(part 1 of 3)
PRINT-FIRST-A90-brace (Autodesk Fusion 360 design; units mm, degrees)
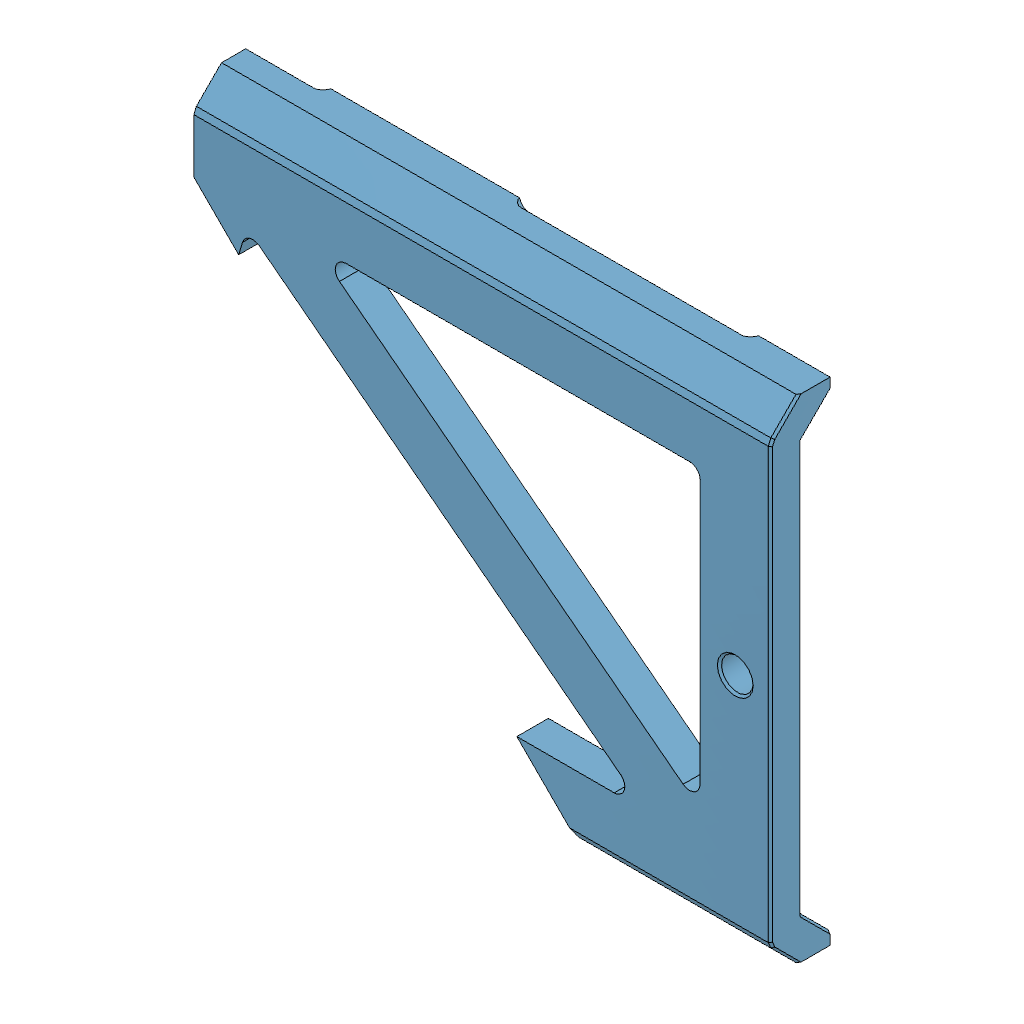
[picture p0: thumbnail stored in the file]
part number: 2026-11-02-20-17-55-344
part number: 2026-11-02-20-17-59-218
part number: 2026-11-02-20-17-59-224
part number: 2026-11-02-20-19-00-695
part number: 2026-11-02-20-19-03-009
part number: 2026-11-02-20-19-04-949
part number: 2026-11-02-20-19-06-912
part number: 2026-11-02-20-19-11-903
part number: 2026-11-02-20-19-12-666
part number: 2026-11-02-20-19-12-978
part number: 2026-11-02-20-19-13-740
part number: 2026-11-02-20-19-14-532
part number: 2026-11-02-20-19-15-361
part number: 2026-11-02-20-19-17-468
part number: 2026-11-02-20-19-19-583
part number: 2026-11-02-20-19-25-638
part number: 2026-11-02-20-19-39-091
parameter "bodyWidth" = 150 comment "Regular octagon across flats; corner diameter is larger."
parameter "bodyLength" = 260 comment "Overall straight length of the shared master blank."
parameter "splitAngle" = 45 comment "Keep this lesson angle at45 degrees."
parameter "faceGap" = 1 comment "Gap between the two printed joint faces."
parameter "wall" = 4.5 comment "Integrated shell and side brace radial thickness."
parameter "faceHalfWidth" = 31.066 (= "bodyWidth * ( sqrt(2) - 1 ) / 2") comment "Half-width of each outer planar facet."
parameter "memberWidth" = 8 comment "Nominal brace and corner chord width in a facet."
parameter "nodeHalfWidth" = 27.066 (= "faceHalfWidth - memberWidth / 2") comment "Chord centerlines measured from facet center."
parameter "jointNodeQ" = 7 comment "First truss skeleton row from the center joint plane."
parameter "endRim" = 10 comment "Uncut axial rim at each distant end."
parameter "endNodeX" = 124 (= "bodyLength / 2 - endRim + memberWidth / 2") comment "Last skeleton row before aperture inset."
parameter "apertureRadius" = 1.5 comment "Rounded internal corners at triangular openings."
parameter "spokeWidth" = 10 comment "Width of each deep bearing bulkhead spoke."
parameter "spokeDepth" = 18 comment "Bulkhead depth normal to the diagonal joint face."
parameter "carrierOD" = 52 comment "Outside of integrated A front bearing carrier."
parameter "rearCarrierClearance" = 46 comment "Internal carrier relief above front bearing shoulder."
parameter "tubeCornerChamfer" = 0.5 comment "Exposed outside octagon corner bevel."
parameter "tubeRimChamfer" = 0.3 comment "End rim and print-contact edge relief."
parameter "cordStation" = 125 (= "bodyLength / 2 - endRim / 2") comment "Load-test cord port center measured along body X."
parameter "bearingOD" = 22 comment "608 measured outside diameter."
parameter "bearingID" = 8 comment "608 bore."
parameter "bearingWidth" = 7 comment "608 width."
parameter "seatAllowance" = 0.2 comment "Trial DIAMETRAL clearance; choose with printed coupon."
parameter "seatDiameter" = 22.2 (= "bearingOD + seatAllowance") comment "Measured fit controls this."
parameter "coreOD" = 44 comment "Bearing holder outer diameter."
parameter "raceRelief" = 19.5 comment "Outer-ring shoulder opening; verify seals."
parameter "frontSeatDepth" = 7.1 comment "0.1 mm outer-ring axial allowance."
parameter "rearSeatDepth" = 7.2 comment "0.2 mm outer-ring axial float."
parameter "shoulder" = 3 comment "Backing behind each bearing seat."
parameter "supportSpacer" = 12 comment "Purchased metal M3 spacer length."
parameter "supportCircle" = 34 comment "Three M3 support bolts."
parameter "supportSpacerOD" = 6 comment "Purchased spacer outside diameter."
parameter "capThickness" = 3 comment "Both printed outer-ring retaining caps."
parameter "m3Clearance" = 3.3 comment "M3 through holes."
parameter "m4Clearance" = 4.3 comment "M4 through holes."
parameter "qFront" = 0.5 (= "faceGap / 2") comment "Front bearing starts at A mating face."
parameter "qFrontBack" = 10.6 (= "qFront + frontSeatDepth + shoulder") comment "End of integrated A holder."
parameter "qRearBase" = 22.6 (= "qFrontBack + supportSpacer") comment "Start of removable rear holder."
parameter "qRearBearing" = 25.6 (= "qRearBase + shoulder") comment "Rear bearing inner end."
parameter "qRearEnd" = 32.8 (= "qRearBearing + rearSeatDepth") comment "Rear holder outer end."
parameter "bearingSpacing" = 25.1 (= "qRearBearing - qFront") comment "Derived support-center spacing, not a bearing rating."
parameter "mountOD" = 76 comment "B mount and F flange outside diameter."
parameter "mountCircle" = 64 comment "Four M4 attachment holes."
parameter "mountOpening" = 50.3 comment "B through opening."
parameter "hubFace" = -23 comment "Metal hub flat mounting face."
parameter "adapterThickness" = 6 comment "F flange and metal compression sleeve length."
parameter "pilotDiameter" = 50 comment "F shallow centering pilot."
parameter "pilotInside" = 34 comment "Clearance around metal hub."
parameter "pilotHeight" = 2 comment "Short pilot only."
parameter "hubHoleSpacing" = 16 comment "Metal Sonic hub square hole spacing."
parameter "sleeveOD" = 8 comment "M4 metal compression sleeves."
parameter "sleeveAllowance" = 0.2 comment "Trial DIAMETRAL sleeve clearance."
parameter "shaftClearance" = 8.5 comment "F clearance hole; not a bearing."
parameter "nutAF" = 7.2 comment "M4 nominal 7 AF nut trial pocket."
parameter "nutDepth" = 4 comment "Open front M4 nut pocket."
parameter "rootRadius" = 1 comment "Hub-to-wall blend."
parameter "entryChamfer" = 0.4 comment "Assembly lead-in."
parameter "bedRelief" = 0.3 comment "Bed-contact edge allowance."
parameter "driverPort" = 5 comment "Clearance for bare3 mm hex-key shafts; bulky bit holders do not fit."
parameter "accessPadWidth" = 12 comment "Reinforced access-port capsule width."
parameter "accessPadExtra" = 2 comment "Local inward reinforcement beyond nominal side wall."
sketch "01 Master Octagon" plane through (0, 0, 0) normal (1, 0, 0) x axis (0, 0, -1)
  line L1 (31.066, 75) -> (75, 31.066)
  line L2 (-31.066, 75) -> (31.066, 75)
  line L3 (-75, 31.066) -> (-31.066, 75)
  line L4 (-75, -31.066) -> (-75, 31.066)
  line L5 (-31.066, -75) -> (-75, -31.066)
  line L6 (31.066, -75) -> (-31.066, -75)
  line L7 (75, -31.066) -> (31.066, -75)
  line L8 (75, 31.066) -> (75, -31.066)
  point P1 (0, 0)
  point P10 (0, 0)
  point P3 (31.066, 75)
  point P8 (31.066, -75)
  coincident P1 P10
  horizontal L2
  dimension "d59" distance P3 P8 = 150 (= "bodyWidth")
extrude "Extrude1" new body sketch "01 Master Octagon" distance 260 (= "bodyLength")
work_plane "WorkPlane1" RotateAngle 45 (= "splitAngle") ExtraOffset 0
split "Split1"
offset_faces "OffsetFaces1" distance -0.5 (= "-faceGap / 2")
offset_faces "OffsetFaces2" distance -0.5 (= "-faceGap / 2")
component_from_bodies "Body->Comp1"
component_from_bodies "Body->Comp2"
shell "Shell1" innerThickness 4.5 (= "wall")
shell "Shell1" innerThickness 4.5 (= "wall")
work_plane "WorkPlane1" RotateAngle -90 ExtraOffset 0
work_plane "WorkPlane2" AlongDistance 75 (= "bodyWidth / 2") ExtraOffset 0
sketch "A Facet 0 Triangle 1" plane through (0, 75, 0) normal (0, 1, 0) x axis (1, 0, 0)
  line L1 (-65.1005, -27.066) -> (-65.1005, 27.066)
  line L2 (60.9665, 27.066) -> (-65.1005, -27.066)
  line L3 (-65.1005, 27.066) -> (60.9665, 27.066)
  line L4 (-61.1005, -20.9953) -> (-61.1005, 23.066)
  line L5 (41.513, 23.066) -> (-61.1005, -20.9953)
  line L6 (-61.1005, 23.066) -> (41.513, 23.066)
  point P1 (0, 0)
  point P2 (-65.1005, 27.066)
  point P3 (-65.1005, -27.066)
  point P4 (60.9665, 27.066)
  dimension "d72" distance P1 P2 = 65.1005 (= "Linear Dimension-2")
  dimension "d73" distance P1 P2 = 27.066 (= "Linear Dimension-3")
  dimension "d74" distance P1 P3 = 65.1005 (= "Linear Dimension-4")
  dimension "d75" distance P1 P3 = 27.066 (= "Linear Dimension-5")
  dimension "d76" distance P1 P4 = 60.9665 (= "Linear Dimension-6")
  dimension "d77" distance P1 P4 = 27.066 (= "Linear Dimension-7")
  dimension "d78" = -4 (= "-memberWidth / 2")
extrude "Extrude1" cut sketch "A Facet 0 Triangle 1" profile of L5 L6 L4 against normal blind 4.7 (magnitude of "-( wall + 0.2 mm )")
sketch "A Facet 0 Triangle 2" plane through (0, 75, 0) normal (0, 1, 0) x axis (1, 0, 0)
  line L1 (60.9665, 27.066) -> (-65.1005, -27.066)
  line L2 (92.4832, -27.066) -> (60.9665, 27.066)
  line L3 (-65.1005, -27.066) -> (92.4832, -27.066)
  line L4 (59.2912, 21.9935) -> (-45.647, -23.066)
  line L5 (85.5258, -23.066) -> (59.2912, 21.9935)
  line L6 (-45.647, -23.066) -> (85.5258, -23.066)
  point P1 (0, 0)
  point P2 (-65.1005, -27.066)
  point P3 (60.9665, 27.066)
  point P4 (92.4832, -27.066)
  dimension "d81" distance P1 P2 = 65.1005 (= "Linear Dimension-2")
  dimension "d82" distance P1 P2 = 27.066 (= "Linear Dimension-3")
  dimension "d83" distance P1 P3 = 60.9665 (= "Linear Dimension-4")
  dimension "d84" distance P1 P3 = 27.066 (= "Linear Dimension-5")
  dimension "d85" distance P1 P4 = 92.4832 (= "Linear Dimension-6")
  dimension "d86" distance P1 P4 = 27.066 (= "Linear Dimension-7")
  dimension "d87" = 4 (= "memberWidth / 2")
extrude "Extrude2" cut sketch "A Facet 0 Triangle 2" profile of L5 L6 L4 against normal blind 4.7 (magnitude of "-( wall + 0.2 mm )")
sketch "A Facet 0 Triangle 3" plane through (0, 75, 0) normal (0, 1, 0) x axis (1, 0, 0)
  line L1 (92.4832, -27.066) -> (60.9665, 27.066)
  line L2 (124, 27.066) -> (92.4832, -27.066)
  line L3 (60.9665, 27.066) -> (124, 27.066)
  line L4 (92.4832, -19.1161) -> (67.924, 23.066)
  line L5 (117.0425, 23.066) -> (92.4832, -19.1161)
  line L6 (67.924, 23.066) -> (117.0425, 23.066)
  point P1 (0, 0)
  point P2 (60.9665, 27.066)
  point P3 (92.4832, -27.066)
  point P4 (124, 27.066)
  dimension "d90" distance P1 P2 = 60.9665 (= "Linear Dimension-2")
  dimension "d91" distance P1 P2 = 27.066 (= "Linear Dimension-3")
  dimension "d92" distance P1 P3 = 92.4832 (= "Linear Dimension-4")
  dimension "d93" distance P1 P3 = 27.066 (= "Linear Dimension-5")
  dimension "d94" distance P1 P4 = 124 (= "Linear Dimension-6")
  dimension "d95" distance P1 P4 = 27.066 (= "Linear Dimension-7")
  dimension "d96" = -4 (= "-memberWidth / 2")
extrude "Extrude3" cut sketch "A Facet 0 Triangle 3" profile of L5 L6 L4 against normal blind 4.7 (magnitude of "-( wall + 0.2 mm )")
sketch "A Facet 0 Triangle 4" plane through (0, 75, 0) normal (0, 1, 0) x axis (1, 0, 0)
  line L1 (124, 27.066) -> (92.4832, -27.066)
  line L2 (124, -27.066) -> (124, 27.066)
  line L3 (92.4832, -27.066) -> (124, -27.066)
  line L4 (120, 12.2459) -> (99.4407, -23.066)
  line L5 (120, -23.066) -> (120, 12.2459)
  line L6 (99.4407, -23.066) -> (120, -23.066)
  point P1 (0, 0)
  point P2 (92.4832, -27.066)
  point P3 (124, 27.066)
  point P4 (124, -27.066)
  dimension "d99" distance P1 P2 = 92.4832 (= "Linear Dimension-2")
  dimension "d100" distance P1 P2 = 27.066 (= "Linear Dimension-3")
  dimension "d101" distance P1 P3 = 124 (= "Linear Dimension-4")
  dimension "d102" distance P1 P3 = 27.066 (= "Linear Dimension-5")
  dimension "d103" distance P1 P4 = 124 (= "Linear Dimension-6")
  dimension "d104" distance P1 P4 = 27.066 (= "Linear Dimension-7")
  dimension "d105" = 4 (= "memberWidth / 2")
extrude "Extrude4" cut sketch "A Facet 0 Triangle 4" profile of L5 L6 L4 against normal blind 4.7 (magnitude of "-( wall + 0.2 mm )")
fillet "Fillet1" radius 1.5 (= "apertureRadius")
work_plane "WorkPlane3" RotateAngle -45 ExtraOffset 0
work_plane "WorkPlane4" AlongDistance 75 (= "bodyWidth / 2") ExtraOffset 0
sketch "A Facet 45 Triangle 1" plane through (0, 53.033, 53.033) normal (0, 0.7071, 0.7071) x axis (1, 0, 0)
  line L1 (-23.9949, -27.066) -> (-62.2721, 27.066)
  line L2 (-0.1814, 27.066) -> (-23.9949, -27.066)
  line L3 (-62.2721, 27.066) -> (-0.1814, 27.066)
  line L4 (-24.81, -18.9852) -> (-54.5447, 23.066)
  line L5 (-6.311, 23.066) -> (-24.81, -18.9852)
  line L6 (-54.5447, 23.066) -> (-6.311, 23.066)
  point P1 (0, 0)
  point P2 (-62.2721, 27.066)
  point P3 (-23.9949, -27.066)
  point P4 (-0.1814, 27.066)
  dimension "d114" distance P1 P2 = 62.2721 (= "Linear Dimension-2")
  dimension "d115" distance P1 P2 = 27.066 (= "Linear Dimension-3")
  dimension "d116" distance P1 P3 = 23.9949 (= "Linear Dimension-4")
  dimension "d117" distance P1 P3 = 27.066 (= "Linear Dimension-5")
  dimension "d118" distance P1 P4 = 0.1814 (= "Linear Dimension-6")
  dimension "d119" distance P1 P4 = 27.066 (= "Linear Dimension-7")
  dimension "d120" = -4 (= "-memberWidth / 2")
extrude "Extrude5" cut sketch "A Facet 45 Triangle 1" profile of L5 L6 L4 against normal blind 4.7 (magnitude of "-( wall + 0.2 mm )")
sketch "A Facet 45 Triangle 2" plane through (0, 53.033, 53.033) normal (0, 0.7071, 0.7071) x axis (1, 0, 0)
  line L1 (-0.1814, 27.066) -> (-23.9949, -27.066)
  line L2 (74.6684, -27.066) -> (-0.1814, 27.066)
  line L3 (-23.9949, -27.066) -> (74.6684, -27.066)
  line L4 (1.4863, 20.9235) -> (-17.8653, -23.066)
  line L5 (62.3117, -23.066) -> (1.4863, 20.9235)
  line L6 (-17.8653, -23.066) -> (62.3117, -23.066)
  point P1 (0, 0)
  point P2 (-23.9949, -27.066)
  point P3 (-0.1814, 27.066)
  point P4 (74.6684, -27.066)
  dimension "d123" distance P1 P2 = 23.9949 (= "Linear Dimension-2")
  dimension "d124" distance P1 P2 = 27.066 (= "Linear Dimension-3")
  dimension "d125" distance P1 P3 = 0.1814 (= "Linear Dimension-4")
  dimension "d126" distance P1 P3 = 27.066 (= "Linear Dimension-5")
  dimension "d127" distance P1 P4 = 74.6684 (= "Linear Dimension-6")
  dimension "d128" distance P1 P4 = 27.066 (= "Linear Dimension-7")
  dimension "d129" = 4 (= "memberWidth / 2")
extrude "Extrude6" cut sketch "A Facet 45 Triangle 2" profile of L5 L6 L4 against normal blind 4.7 (magnitude of "-( wall + 0.2 mm )")
sketch "A Facet 45 Triangle 3" plane through (0, 53.033, 53.033) normal (0, 0.7071, 0.7071) x axis (1, 0, 0)
  line L1 (74.6684, -27.066) -> (-0.1814, 27.066)
  line L2 (124, 27.066) -> (74.6684, -27.066)
  line L3 (-0.1814, 27.066) -> (124, 27.066)
  line L4 (74.1179, -21.7315) -> (12.1753, 23.066)
  line L5 (114.9429, 23.066) -> (74.1179, -21.7315)
  line L6 (12.1753, 23.066) -> (114.9429, 23.066)
  point P1 (0, 0)
  point P2 (-0.1814, 27.066)
  point P3 (74.6684, -27.066)
  point P4 (124, 27.066)
  dimension "d132" distance P1 P2 = 0.1814 (= "Linear Dimension-2")
  dimension "d133" distance P1 P2 = 27.066 (= "Linear Dimension-3")
  dimension "d134" distance P1 P3 = 74.6684 (= "Linear Dimension-4")
  dimension "d135" distance P1 P3 = 27.066 (= "Linear Dimension-5")
  dimension "d136" distance P1 P4 = 124 (= "Linear Dimension-6")
  dimension "d137" distance P1 P4 = 27.066 (= "Linear Dimension-7")
  dimension "d138" = -4 (= "-memberWidth / 2")
extrude "Extrude7" cut sketch "A Facet 45 Triangle 3" profile of L5 L6 L4 against normal blind 4.7 (magnitude of "-( wall + 0.2 mm )")
sketch "A Facet 45 Triangle 4" plane through (0, 53.033, 53.033) normal (0, 0.7071, 0.7071) x axis (1, 0, 0)
  line L1 (124, 27.066) -> (74.6684, -27.066)
  line L2 (124, -27.066) -> (124, 27.066)
  line L3 (74.6684, -27.066) -> (124, -27.066)
  line L4 (120, 16.7383) -> (83.7255, -23.066)
  line L5 (120, -23.066) -> (120, 16.7383)
  line L6 (83.7255, -23.066) -> (120, -23.066)
  point P1 (0, 0)
  point P2 (74.6684, -27.066)
  point P3 (124, 27.066)
  point P4 (124, -27.066)
  dimension "d141" distance P1 P2 = 74.6684 (= "Linear Dimension-2")
  dimension "d142" distance P1 P2 = 27.066 (= "Linear Dimension-3")
  dimension "d143" distance P1 P3 = 124 (= "Linear Dimension-4")
  dimension "d144" distance P1 P3 = 27.066 (= "Linear Dimension-5")
  dimension "d145" distance P1 P4 = 124 (= "Linear Dimension-6")
  dimension "d146" distance P1 P4 = 27.066 (= "Linear Dimension-7")
  dimension "d147" = 4 (= "memberWidth / 2")
extrude "Extrude8" cut sketch "A Facet 45 Triangle 4" profile of L5 L6 L4 against normal blind 4.7 (magnitude of "-( wall + 0.2 mm )")
fillet "Fillet2" radius 1.5 (= "apertureRadius")
work_plane "WorkPlane5" RotateAngle 0 ExtraOffset 0
work_plane "WorkPlane6" AlongDistance 75 (= "bodyWidth / 2") ExtraOffset 0
sketch "A Facet 90 Triangle 1" plane through (0, 0, 75) normal (0, 0, 1) x axis (1, 0, 0)
  line L1 (36.9655, -27.066) -> (-17.1665, 27.066)
  line L2 (53.4167, 27.066) -> (36.9655, -27.066)
  line L3 (-17.1665, 27.066) -> (53.4167, 27.066)
  line L4 (35.0777, -19.5214) -> (-7.5097, 23.066)
  line L5 (48.0205, 23.066) -> (35.0777, -19.5214)
  line L6 (-7.5097, 23.066) -> (48.0205, 23.066)
  point P1 (0, 0)
  point P2 (-17.1665, 27.066)
  point P3 (36.9655, -27.066)
  point P4 (53.4167, 27.066)
  dimension "d156" distance P1 P2 = 17.1665 (= "Linear Dimension-2")
  dimension "d157" distance P1 P2 = 27.066 (= "Linear Dimension-3")
  dimension "d158" distance P1 P3 = 36.9655 (= "Linear Dimension-4")
  dimension "d159" distance P1 P3 = 27.066 (= "Linear Dimension-5")
  dimension "d160" distance P1 P4 = 53.4167 (= "Linear Dimension-6")
  dimension "d161" distance P1 P4 = 27.066 (= "Linear Dimension-7")
  dimension "d162" = -4 (= "-memberWidth / 2")
extrude "Extrude9" cut sketch "A Facet 90 Triangle 1" profile of L5 L6 L4 against normal blind 4.7 (magnitude of "-( wall + 0.2 mm )")
sketch "A Facet 90 Triangle 2" plane through (0, 0, 75) normal (0, 0, 1) x axis (1, 0, 0)
  line L1 (53.4167, 27.066) -> (36.9655, -27.066)
  line L2 (124, -27.066) -> (53.4167, 27.066)
  line L3 (36.9655, -27.066) -> (124, -27.066)
  line L4 (55.5648, 20.3777) -> (42.3618, -23.066)
  line L5 (112.2115, -23.066) -> (55.5648, 20.3777)
  line L6 (42.3618, -23.066) -> (112.2115, -23.066)
  point P1 (0, 0)
  point P2 (36.9655, -27.066)
  point P3 (53.4167, 27.066)
  point P4 (124, -27.066)
  dimension "d165" distance P1 P2 = 36.9655 (= "Linear Dimension-2")
  dimension "d166" distance P1 P2 = 27.066 (= "Linear Dimension-3")
  dimension "d167" distance P1 P3 = 53.4167 (= "Linear Dimension-4")
  dimension "d168" distance P1 P3 = 27.066 (= "Linear Dimension-5")
  dimension "d169" distance P1 P4 = 124 (= "Linear Dimension-6")
  dimension "d170" distance P1 P4 = 27.066 (= "Linear Dimension-7")
  dimension "d171" = 4 (= "memberWidth / 2")
extrude "Extrude10" cut sketch "A Facet 90 Triangle 2" profile of L5 L6 L4 against normal blind 4.7 (magnitude of "-( wall + 0.2 mm )")
sketch "A Facet 90 Triangle 3" plane through (0, 0, 75) normal (0, 0, 1) x axis (1, 0, 0)
  line L1 (124, -27.066) -> (53.4167, 27.066)
  line L2 (124, 27.066) -> (124, -27.066)
  line L3 (53.4167, 27.066) -> (124, 27.066)
  line L4 (120, -18.9574) -> (65.2053, 23.066)
  line L5 (120, 23.066) -> (120, -18.9574)
  line L6 (65.2053, 23.066) -> (120, 23.066)
  point P1 (0, 0)
  point P2 (53.4167, 27.066)
  point P3 (124, -27.066)
  point P4 (124, 27.066)
  dimension "d174" distance P1 P2 = 53.4167 (= "Linear Dimension-2")
  dimension "d175" distance P1 P2 = 27.066 (= "Linear Dimension-3")
  dimension "d176" distance P1 P3 = 124 (= "Linear Dimension-4")
  dimension "d177" distance P1 P3 = 27.066 (= "Linear Dimension-5")
  dimension "d178" distance P1 P4 = 124 (= "Linear Dimension-6")
  dimension "d179" distance P1 P4 = 27.066 (= "Linear Dimension-7")
  dimension "d180" = -4 (= "-memberWidth / 2")
extrude "Extrude11" cut sketch "A Facet 90 Triangle 3" profile of L5 L6 L4 against normal blind 4.7 (magnitude of "-( wall + 0.2 mm )")
fillet "Fillet3" radius 1.5 (= "apertureRadius")
work_plane "WorkPlane7" RotateAngle 45 ExtraOffset 0
work_plane "WorkPlane8" AlongDistance 75 (= "bodyWidth / 2") ExtraOffset 0
sketch "A Facet 135 Triangle 1" plane through (0, -53.033, 53.033) normal (0, -0.7071, 0.7071) x axis (1, 0, 0)
  line L1 (82.0711, -27.066) -> (43.7939, 27.066)
  line L2 (124, 27.066) -> (82.0711, -27.066)
  line L3 (43.7939, 27.066) -> (124, 27.066)
  line L4 (82.2175, -20.3449) -> (51.5213, 23.066)
  line L5 (115.8422, 23.066) -> (82.2175, -20.3449)
  line L6 (51.5213, 23.066) -> (115.8422, 23.066)
  point P1 (0, 0)
  point P2 (43.7939, 27.066)
  point P3 (82.0711, -27.066)
  point P4 (124, 27.066)
  dimension "d189" distance P1 P2 = 43.7939 (= "Linear Dimension-2")
  dimension "d190" distance P1 P2 = 27.066 (= "Linear Dimension-3")
  dimension "d191" distance P1 P3 = 82.0711 (= "Linear Dimension-4")
  dimension "d192" distance P1 P3 = 27.066 (= "Linear Dimension-5")
  dimension "d193" distance P1 P4 = 124 (= "Linear Dimension-6")
  dimension "d194" distance P1 P4 = 27.066 (= "Linear Dimension-7")
  dimension "d195" = -4 (= "-memberWidth / 2")
extrude "Extrude12" cut sketch "A Facet 135 Triangle 1" profile of L5 L6 L4 against normal blind 4.7 (magnitude of "-( wall + 0.2 mm )")
sketch "A Facet 135 Triangle 2" plane through (0, -53.033, 53.033) normal (0, -0.7071, 0.7071) x axis (1, 0, 0)
  line L1 (124, 27.066) -> (82.0711, -27.066)
  line L2 (124, -27.066) -> (124, 27.066)
  line L3 (82.0711, -27.066) -> (124, -27.066)
  line L4 (120, 15.3697) -> (90.2289, -23.066)
  line L5 (120, -23.066) -> (120, 15.3697)
  line L6 (90.2289, -23.066) -> (120, -23.066)
  point P1 (0, 0)
  point P2 (82.0711, -27.066)
  point P3 (124, 27.066)
  point P4 (124, -27.066)
  dimension "d198" distance P1 P2 = 82.0711 (= "Linear Dimension-2")
  dimension "d199" distance P1 P2 = 27.066 (= "Linear Dimension-3")
  dimension "d200" distance P1 P3 = 124 (= "Linear Dimension-4")
  dimension "d201" distance P1 P3 = 27.066 (= "Linear Dimension-5")
  dimension "d202" distance P1 P4 = 124 (= "Linear Dimension-6")
  dimension "d203" distance P1 P4 = 27.066 (= "Linear Dimension-7")
  dimension "d204" = 4 (= "memberWidth / 2")
extrude "Extrude13" cut sketch "A Facet 135 Triangle 2" profile of L5 L6 L4 against normal blind 4.7 (magnitude of "-( wall + 0.2 mm )")
fillet "Fillet4" radius 1.5 (= "apertureRadius")
work_plane "WorkPlane9" RotateAngle 90 ExtraOffset 0
work_plane "WorkPlane10" AlongDistance 75 (= "bodyWidth / 2") ExtraOffset 0
sketch "A Facet 180 Triangle 1" plane through (0, -75, 0) normal (0, -1, 0) x axis (-1, 0, 0)
  line L1 (-84.8995, 27.066) -> (-84.8995, -27.066)
  line L2 (-124, -27.066) -> (-84.8995, 27.066)
  line L3 (-84.8995, -27.066) -> (-124, -27.066)
  line L4 (-88.8995, 14.697) -> (-88.8995, -23.066)
  line L5 (-116.1764, -23.066) -> (-88.8995, 14.697)
  line L6 (-88.8995, -23.066) -> (-116.1764, -23.066)
  point P1 (0, 0)
  point P2 (-84.8995, -27.066)
  point P3 (-84.8995, 27.066)
  point P4 (-124, -27.066)
  dimension "d213" distance P1 P2 = 84.8995 (= "Linear Dimension-2")
  dimension "d214" distance P1 P2 = 27.066 (= "Linear Dimension-3")
  dimension "d215" distance P1 P3 = 84.8995 (= "Linear Dimension-4")
  dimension "d216" distance P1 P3 = 27.066 (= "Linear Dimension-5")
  dimension "d217" distance P1 P4 = 124 (= "Linear Dimension-6")
  dimension "d218" distance P1 P4 = 27.066 (= "Linear Dimension-7")
  dimension "d219" = -4 (= "-memberWidth / 2")
extrude "Extrude14" cut sketch "A Facet 180 Triangle 1" profile of L5 L6 L4 against normal blind 4.7 (magnitude of "-( wall + 0.2 mm )")
sketch "A Facet 180 Triangle 2" plane through (0, -75, 0) normal (0, -1, 0) x axis (-1, 0, 0)
  line L1 (-124, -27.066) -> (-84.8995, 27.066)
  line L2 (-124, 27.066) -> (-124, -27.066)
  line L3 (-84.8995, 27.066) -> (-124, 27.066)
  line L4 (-120, -14.697) -> (-92.7231, 23.066)
  line L5 (-120, 23.066) -> (-120, -14.697)
  line L6 (-92.7231, 23.066) -> (-120, 23.066)
  point P1 (0, 0)
  point P2 (-84.8995, 27.066)
  point P3 (-124, -27.066)
  point P4 (-124, 27.066)
  dimension "d222" distance P1 P2 = 84.8995 (= "Linear Dimension-2")
  dimension "d223" distance P1 P2 = 27.066 (= "Linear Dimension-3")
  dimension "d224" distance P1 P3 = 124 (= "Linear Dimension-4")
  dimension "d225" distance P1 P3 = 27.066 (= "Linear Dimension-5")
  dimension "d226" distance P1 P4 = 124 (= "Linear Dimension-6")
  dimension "d227" distance P1 P4 = 27.066 (= "Linear Dimension-7")
  dimension "d228" = 4 (= "memberWidth / 2")
extrude "Extrude15" cut sketch "A Facet 180 Triangle 2" profile of L5 L6 L4 against normal blind 4.7 (magnitude of "-( wall + 0.2 mm )")
fillet "Fillet5" radius 1.5 (= "apertureRadius")
work_plane "WorkPlane11" RotateAngle 135 ExtraOffset 0
work_plane "WorkPlane12" AlongDistance 75 (= "bodyWidth / 2") ExtraOffset 0
sketch "A Facet 225 Triangle 1" plane through (0, -53.033, -53.033) normal (0, -0.7071, -0.7071) x axis (1, 0, 0)
  line L1 (43.7939, -27.066) -> (82.0711, 27.066)
  line L2 (124, 27.066) -> (43.7939, -27.066)
  line L3 (82.0711, 27.066) -> (124, 27.066)
  line L4 (59.6927, -11.51) -> (84.1416, 23.066)
  line L5 (110.9231, 23.066) -> (59.6927, -11.51)
  line L6 (84.1416, 23.066) -> (110.9231, 23.066)
  point P1 (0, 0)
  point P2 (82.0711, 27.066)
  point P3 (43.7939, -27.066)
  point P4 (124, 27.066)
  dimension "d237" distance P1 P2 = 82.0711 (= "Linear Dimension-2")
  dimension "d238" distance P1 P2 = 27.066 (= "Linear Dimension-3")
  dimension "d239" distance P1 P3 = 43.7939 (= "Linear Dimension-4")
  dimension "d240" distance P1 P3 = 27.066 (= "Linear Dimension-5")
  dimension "d241" distance P1 P4 = 124 (= "Linear Dimension-6")
  dimension "d242" distance P1 P4 = 27.066 (= "Linear Dimension-7")
  dimension "d243" = -4 (= "-memberWidth / 2")
extrude "Extrude16" cut sketch "A Facet 225 Triangle 1" profile of L5 L6 L4 against normal blind 4.7 (magnitude of "-( wall + 0.2 mm )")
sketch "A Facet 225 Triangle 2" plane through (0, -53.033, -53.033) normal (0, -0.7071, -0.7071) x axis (1, 0, 0)
  line L1 (124, 27.066) -> (43.7939, -27.066)
  line L2 (124, -27.066) -> (124, 27.066)
  line L3 (43.7939, -27.066) -> (124, -27.066)
  line L4 (120, 19.5406) -> (56.8709, -23.066)
  line L5 (120, -23.066) -> (120, 19.5406)
  line L6 (56.8709, -23.066) -> (120, -23.066)
  point P1 (0, 0)
  point P2 (43.7939, -27.066)
  point P3 (124, 27.066)
  point P4 (124, -27.066)
  dimension "d246" distance P1 P2 = 43.7939 (= "Linear Dimension-2")
  dimension "d247" distance P1 P2 = 27.066 (= "Linear Dimension-3")
  dimension "d248" distance P1 P3 = 124 (= "Linear Dimension-4")
  dimension "d249" distance P1 P3 = 27.066 (= "Linear Dimension-5")
  dimension "d250" distance P1 P4 = 124 (= "Linear Dimension-6")
  dimension "d251" distance P1 P4 = 27.066 (= "Linear Dimension-7")
  dimension "d252" = 4 (= "memberWidth / 2")
extrude "Extrude17" cut sketch "A Facet 225 Triangle 2" profile of L5 L6 L4 against normal blind 4.7 (magnitude of "-( wall + 0.2 mm )")
fillet "Fillet6" radius 1.5 (= "apertureRadius")
work_plane "WorkPlane13" RotateAngle 180 ExtraOffset 0
work_plane "WorkPlane14" AlongDistance 75 (= "bodyWidth / 2") ExtraOffset 0
sketch "A Facet 270 Triangle 1" plane through (0, 0, -75) normal (0, 0, -1) x axis (-1, 0, 0)
  line L1 (17.1665, 27.066) -> (-36.9655, -27.066)
  line L2 (-80.4828, -27.066) -> (17.1665, 27.066)
  line L3 (-36.9655, -27.066) -> (-80.4828, -27.066)
  line L4 (-5.7896, 9.7668) -> (-38.6224, -23.066)
  line L5 (-65.0169, -23.066) -> (-5.7896, 9.7668)
  line L6 (-38.6224, -23.066) -> (-65.0169, -23.066)
  point P1 (0, 0)
  point P2 (-36.9655, -27.066)
  point P3 (17.1665, 27.066)
  point P4 (-80.4828, -27.066)
  dimension "d261" distance P1 P2 = 36.9655 (= "Linear Dimension-2")
  dimension "d262" distance P1 P2 = 27.066 (= "Linear Dimension-3")
  dimension "d263" distance P1 P3 = 17.1665 (= "Linear Dimension-4")
  dimension "d264" distance P1 P3 = 27.066 (= "Linear Dimension-5")
  dimension "d265" distance P1 P4 = 80.4828 (= "Linear Dimension-6")
  dimension "d266" distance P1 P4 = 27.066 (= "Linear Dimension-7")
  dimension "d267" = -4 (= "-memberWidth / 2")
extrude "Extrude18" cut sketch "A Facet 270 Triangle 1" profile of L5 L6 L4 against normal blind 4.7 (magnitude of "-( wall + 0.2 mm )")
sketch "A Facet 270 Triangle 2" plane through (0, 0, -75) normal (0, 0, -1) x axis (-1, 0, 0)
  line L1 (-80.4828, -27.066) -> (17.1665, 27.066)
  line L2 (-124, 27.066) -> (-80.4828, -27.066)
  line L3 (17.1665, 27.066) -> (-124, 27.066)
  line L4 (-79.4759, -21.9343) -> (1.7007, 23.066)
  line L5 (-115.6521, 23.066) -> (-79.4759, -21.9343)
  line L6 (1.7007, 23.066) -> (-115.6521, 23.066)
  point P1 (0, 0)
  point P2 (17.1665, 27.066)
  point P3 (-80.4828, -27.066)
  point P4 (-124, 27.066)
  dimension "d270" distance P1 P2 = 17.1665 (= "Linear Dimension-2")
  dimension "d271" distance P1 P2 = 27.066 (= "Linear Dimension-3")
  dimension "d272" distance P1 P3 = 80.4828 (= "Linear Dimension-4")
  dimension "d273" distance P1 P3 = 27.066 (= "Linear Dimension-5")
  dimension "d274" distance P1 P4 = 124 (= "Linear Dimension-6")
  dimension "d275" distance P1 P4 = 27.066 (= "Linear Dimension-7")
  dimension "d276" = 4 (= "memberWidth / 2")
extrude "Extrude19" cut sketch "A Facet 270 Triangle 2" profile of L5 L6 L4 against normal blind 4.7 (magnitude of "-( wall + 0.2 mm )")
sketch "A Facet 270 Triangle 3" plane through (0, 0, -75) normal (0, 0, -1) x axis (-1, 0, 0)
  line L1 (-124, 27.066) -> (-80.4828, -27.066)
  line L2 (-124, -27.066) -> (-124, 27.066)
  line L3 (-80.4828, -27.066) -> (-124, -27.066)
  line L4 (-120, 15.7062) -> (-88.8307, -23.066)
  line L5 (-120, -23.066) -> (-120, 15.7062)
  line L6 (-88.8307, -23.066) -> (-120, -23.066)
  point P1 (0, 0)
  point P2 (-80.4828, -27.066)
  point P3 (-124, 27.066)
  point P4 (-124, -27.066)
  dimension "d279" distance P1 P2 = 80.4828 (= "Linear Dimension-2")
  dimension "d280" distance P1 P2 = 27.066 (= "Linear Dimension-3")
  dimension "d281" distance P1 P3 = 124 (= "Linear Dimension-4")
  dimension "d282" distance P1 P3 = 27.066 (= "Linear Dimension-5")
  dimension "d283" distance P1 P4 = 124 (= "Linear Dimension-6")
  dimension "d284" distance P1 P4 = 27.066 (= "Linear Dimension-7")
  dimension "d285" = -4 (= "-memberWidth / 2")
extrude "Extrude20" cut sketch "A Facet 270 Triangle 3" profile of L5 L6 L4 against normal blind 4.7 (magnitude of "-( wall + 0.2 mm )")
fillet "Fillet7" radius 1.5 (= "apertureRadius")
work_plane "WorkPlane15" RotateAngle 225 ExtraOffset 0
work_plane "WorkPlane16" AlongDistance 75 (= "bodyWidth / 2") ExtraOffset 0
sketch "A Facet 315 Triangle 1" plane through (0, 53.033, -53.033) normal (0, 0.7071, -0.7071) x axis (1, 0, 0)
  line L1 (-62.2721, -27.066) -> (-23.9949, 27.066)
  line L2 (25.3367, 27.066) -> (-62.2721, -27.066)
  line L3 (-23.9949, 27.066) -> (25.3367, 27.066)
  line L4 (-47.6674, -13.34) -> (-21.9244, 23.066)
  line L5 (11.2532, 23.066) -> (-47.6674, -13.34)
  line L6 (-21.9244, 23.066) -> (11.2532, 23.066)
  point P1 (0, 0)
  point P2 (-23.9949, 27.066)
  point P3 (-62.2721, -27.066)
  point P4 (25.3367, 27.066)
  dimension "d294" distance P1 P2 = 23.9949 (= "Linear Dimension-2")
  dimension "d295" distance P1 P2 = 27.066 (= "Linear Dimension-3")
  dimension "d296" distance P1 P3 = 62.2721 (= "Linear Dimension-4")
  dimension "d297" distance P1 P3 = 27.066 (= "Linear Dimension-5")
  dimension "d298" distance P1 P4 = 25.3367 (= "Linear Dimension-6")
  dimension "d299" distance P1 P4 = 27.066 (= "Linear Dimension-7")
  dimension "d300" = -4 (= "-memberWidth / 2")
extrude "Extrude21" cut sketch "A Facet 315 Triangle 1" profile of L5 L6 L4 against normal blind 4.7 (magnitude of "-( wall + 0.2 mm )")
sketch "A Facet 315 Triangle 2" plane through (0, 53.033, -53.033) normal (0, 0.7071, -0.7071) x axis (1, 0, 0)
  line L1 (25.3367, 27.066) -> (-62.2721, -27.066)
  line L2 (61.9093, -27.066) -> (25.3367, 27.066)
  line L3 (-62.2721, -27.066) -> (61.9093, -27.066)
  line L4 (24.1722, 21.6445) -> (-48.1886, -23.066)
  line L5 (54.3795, -23.066) -> (24.1722, 21.6445)
  line L6 (-48.1886, -23.066) -> (54.3795, -23.066)
  point P1 (0, 0)
  point P2 (-62.2721, -27.066)
  point P3 (25.3367, 27.066)
  point P4 (61.9093, -27.066)
  dimension "d303" distance P1 P2 = 62.2721 (= "Linear Dimension-2")
  dimension "d304" distance P1 P2 = 27.066 (= "Linear Dimension-3")
  dimension "d305" distance P1 P3 = 25.3367 (= "Linear Dimension-4")
  dimension "d306" distance P1 P3 = 27.066 (= "Linear Dimension-5")
  dimension "d307" distance P1 P4 = 61.9093 (= "Linear Dimension-6")
  dimension "d308" distance P1 P4 = 27.066 (= "Linear Dimension-7")
  dimension "d309" = 4 (= "memberWidth / 2")
extrude "Extrude22" cut sketch "A Facet 315 Triangle 2" profile of L5 L6 L4 against normal blind 4.7 (magnitude of "-( wall + 0.2 mm )")
sketch "A Facet 315 Triangle 3" plane through (0, 53.033, -53.033) normal (0, 0.7071, -0.7071) x axis (1, 0, 0)
  line L1 (61.9093, -27.066) -> (25.3367, 27.066)
  line L2 (124, 27.066) -> (61.9093, -27.066)
  line L3 (25.3367, 27.066) -> (124, 27.066)
  line L4 (62.6909, -21.0779) -> (32.8665, 23.066)
  line L5 (113.325, 23.066) -> (62.6909, -21.0779)
  line L6 (32.8665, 23.066) -> (113.325, 23.066)
  point P1 (0, 0)
  point P2 (25.3367, 27.066)
  point P3 (61.9093, -27.066)
  point P4 (124, 27.066)
  dimension "d312" distance P1 P2 = 25.3367 (= "Linear Dimension-2")
  dimension "d313" distance P1 P2 = 27.066 (= "Linear Dimension-3")
  dimension "d314" distance P1 P3 = 61.9093 (= "Linear Dimension-4")
  dimension "d315" distance P1 P3 = 27.066 (= "Linear Dimension-5")
  dimension "d316" distance P1 P4 = 124 (= "Linear Dimension-6")
  dimension "d317" distance P1 P4 = 27.066 (= "Linear Dimension-7")
  dimension "d318" = -4 (= "-memberWidth / 2")
extrude "Extrude23" cut sketch "A Facet 315 Triangle 3" profile of L5 L6 L4 against normal blind 4.7 (magnitude of "-( wall + 0.2 mm )")
sketch "A Facet 315 Triangle 4" plane through (0, 53.033, -53.033) normal (0, 0.7071, -0.7071) x axis (1, 0, 0)
  line L1 (124, 27.066) -> (61.9093, -27.066)
  line L2 (124, -27.066) -> (124, 27.066)
  line L3 (61.9093, -27.066) -> (124, -27.066)
  line L4 (120, 18.272) -> (72.5843, -23.066)
  line L5 (120, -23.066) -> (120, 18.272)
  line L6 (72.5843, -23.066) -> (120, -23.066)
  point P1 (0, 0)
  point P2 (61.9093, -27.066)
  point P3 (124, 27.066)
  point P4 (124, -27.066)
  dimension "d321" distance P1 P2 = 61.9093 (= "Linear Dimension-2")
  dimension "d322" distance P1 P2 = 27.066 (= "Linear Dimension-3")
  dimension "d323" distance P1 P3 = 124 (= "Linear Dimension-4")
  dimension "d324" distance P1 P3 = 27.066 (= "Linear Dimension-5")
  dimension "d325" distance P1 P4 = 124 (= "Linear Dimension-6")
  dimension "d326" distance P1 P4 = 27.066 (= "Linear Dimension-7")
  dimension "d327" = 4 (= "memberWidth / 2")
extrude "Extrude24" cut sketch "A Facet 315 Triangle 4" profile of L5 L6 L4 against normal blind 4.7 (magnitude of "-( wall + 0.2 mm )")
fillet "Fillet8" radius 1.5 (= "apertureRadius")
work_plane "WorkPlane1" RotateAngle -90 ExtraOffset 0
work_plane "WorkPlane2" AlongDistance 75 (= "bodyWidth / 2") ExtraOffset 0
sketch "B Facet 0 Triangle 1" plane through (0, 75, 0) normal (0, 1, 0) x axis (1, 0, 0)
  line L1 (-84.8995, -27.066) -> (-84.8995, 27.066)
  line L2 (-124, 27.066) -> (-84.8995, -27.066)
  line L3 (-84.8995, 27.066) -> (-124, 27.066)
  line L4 (-88.8995, -14.697) -> (-88.8995, 23.066)
  line L5 (-116.1764, 23.066) -> (-88.8995, -14.697)
  line L6 (-88.8995, 23.066) -> (-116.1764, 23.066)
  point P1 (0, 0)
  point P2 (-84.8995, 27.066)
  point P3 (-84.8995, -27.066)
  point P4 (-124, 27.066)
  dimension "d336" distance P1 P2 = 84.8995 (= "Linear Dimension-2")
  dimension "d337" distance P1 P2 = 27.066 (= "Linear Dimension-3")
  dimension "d338" distance P1 P3 = 84.8995 (= "Linear Dimension-4")
  dimension "d339" distance P1 P3 = 27.066 (= "Linear Dimension-5")
  dimension "d340" distance P1 P4 = 124 (= "Linear Dimension-6")
  dimension "d341" distance P1 P4 = 27.066 (= "Linear Dimension-7")
  dimension "d342" = 4 (= "memberWidth / 2")
extrude "Extrude1" cut sketch "B Facet 0 Triangle 1" profile of L5 L6 L4 against normal blind 4.7 (magnitude of "-( wall + 0.2 mm )")
sketch "B Facet 0 Triangle 2" plane through (0, 75, 0) normal (0, 1, 0) x axis (1, 0, 0)
  line L1 (-124, 27.066) -> (-84.8995, -27.066)
  line L2 (-124, -27.066) -> (-124, 27.066)
  line L3 (-84.8995, -27.066) -> (-124, -27.066)
  line L4 (-120, 14.697) -> (-92.7231, -23.066)
  line L5 (-120, -23.066) -> (-120, 14.697)
  line L6 (-92.7231, -23.066) -> (-120, -23.066)
  point P1 (0, 0)
  point P2 (-84.8995, -27.066)
  point P3 (-124, 27.066)
  point P4 (-124, -27.066)
  dimension "d345" distance P1 P2 = 84.8995 (= "Linear Dimension-2")
  dimension "d346" distance P1 P2 = 27.066 (= "Linear Dimension-3")
  dimension "d347" distance P1 P3 = 124 (= "Linear Dimension-4")
  dimension "d348" distance P1 P3 = 27.066 (= "Linear Dimension-5")
  dimension "d349" distance P1 P4 = 124 (= "Linear Dimension-6")
  dimension "d350" distance P1 P4 = 27.066 (= "Linear Dimension-7")
  dimension "d351" = -4 (= "-memberWidth / 2")
extrude "Extrude2" cut sketch "B Facet 0 Triangle 2" profile of L5 L6 L4 against normal blind 4.7 (magnitude of "-( wall + 0.2 mm )")
fillet "Fillet1" radius 1.5 (= "apertureRadius")
work_plane "WorkPlane3" RotateAngle -45 ExtraOffset 0
work_plane "WorkPlane4" AlongDistance 75 (= "bodyWidth / 2") ExtraOffset 0
sketch "B Facet 45 Triangle 1" plane through (0, 53.033, 53.033) normal (0, 0.7071, 0.7071) x axis (1, 0, 0)
  line L1 (-43.7939, -27.066) -> (-82.0711, 27.066)
  line L2 (-124, 27.066) -> (-43.7939, -27.066)
  line L3 (-82.0711, 27.066) -> (-124, 27.066)
  line L4 (-59.6927, -11.51) -> (-84.1416, 23.066)
  line L5 (-110.9231, 23.066) -> (-59.6927, -11.51)
  line L6 (-84.1416, 23.066) -> (-110.9231, 23.066)
  point P1 (0, 0)
  point P2 (-82.0711, 27.066)
  point P3 (-43.7939, -27.066)
  point P4 (-124, 27.066)
  dimension "d360" distance P1 P2 = 82.0711 (= "Linear Dimension-2")
  dimension "d361" distance P1 P2 = 27.066 (= "Linear Dimension-3")
  dimension "d362" distance P1 P3 = 43.7939 (= "Linear Dimension-4")
  dimension "d363" distance P1 P3 = 27.066 (= "Linear Dimension-5")
  dimension "d364" distance P1 P4 = 124 (= "Linear Dimension-6")
  dimension "d365" distance P1 P4 = 27.066 (= "Linear Dimension-7")
  dimension "d366" = 4 (= "memberWidth / 2")
extrude "Extrude3" cut sketch "B Facet 45 Triangle 1" profile of L5 L6 L4 against normal blind 4.7 (magnitude of "-( wall + 0.2 mm )")
sketch "B Facet 45 Triangle 2" plane through (0, 53.033, 53.033) normal (0, 0.7071, 0.7071) x axis (1, 0, 0)
  line L1 (-124, 27.066) -> (-43.7939, -27.066)
  line L2 (-124, -27.066) -> (-124, 27.066)
  line L3 (-43.7939, -27.066) -> (-124, -27.066)
  line L4 (-120, 19.5406) -> (-56.8709, -23.066)
  line L5 (-120, -23.066) -> (-120, 19.5406)
  line L6 (-56.8709, -23.066) -> (-120, -23.066)
  point P1 (0, 0)
  point P2 (-43.7939, -27.066)
  point P3 (-124, 27.066)
  point P4 (-124, -27.066)
  dimension "d369" distance P1 P2 = 43.7939 (= "Linear Dimension-2")
  dimension "d370" distance P1 P2 = 27.066 (= "Linear Dimension-3")
  dimension "d371" distance P1 P3 = 124 (= "Linear Dimension-4")
  dimension "d372" distance P1 P3 = 27.066 (= "Linear Dimension-5")
  dimension "d373" distance P1 P4 = 124 (= "Linear Dimension-6")
  dimension "d374" distance P1 P4 = 27.066 (= "Linear Dimension-7")
  dimension "d375" = -4 (= "-memberWidth / 2")
extrude "Extrude4" cut sketch "B Facet 45 Triangle 2" profile of L5 L6 L4 against normal blind 4.7 (magnitude of "-( wall + 0.2 mm )")
fillet "Fillet2" radius 1.5 (= "apertureRadius")
work_plane "WorkPlane5" RotateAngle 0 ExtraOffset 0
work_plane "WorkPlane6" AlongDistance 75 (= "bodyWidth / 2") ExtraOffset 0
sketch "B Facet 90 Triangle 1" plane through (0, 0, 75) normal (0, 0, 1) x axis (1, 0, 0)
  line L1 (-36.9655, 27.066) -> (17.1665, -27.066)
  line L2 (-53.4167, -27.066) -> (-36.9655, 27.066)
  line L3 (17.1665, -27.066) -> (-53.4167, -27.066)
  line L4 (-35.0777, 19.5214) -> (7.5097, -23.066)
  line L5 (-48.0205, -23.066) -> (-35.0777, 19.5214)
  line L6 (7.5097, -23.066) -> (-48.0205, -23.066)
  point P1 (0, 0)
  point P2 (17.1665, -27.066)
  point P3 (-36.9655, 27.066)
  point P4 (-53.4167, -27.066)
  dimension "d384" distance P1 P2 = 17.1665 (= "Linear Dimension-2")
  dimension "d385" distance P1 P2 = 27.066 (= "Linear Dimension-3")
  dimension "d386" distance P1 P3 = 36.9655 (= "Linear Dimension-4")
  dimension "d387" distance P1 P3 = 27.066 (= "Linear Dimension-5")
  dimension "d388" distance P1 P4 = 53.4167 (= "Linear Dimension-6")
  dimension "d389" distance P1 P4 = 27.066 (= "Linear Dimension-7")
  dimension "d390" = -4 (= "-memberWidth / 2")
extrude "Extrude5" cut sketch "B Facet 90 Triangle 1" profile of L5 L6 L4 against normal blind 4.7 (magnitude of "-( wall + 0.2 mm )")
sketch "B Facet 90 Triangle 2" plane through (0, 0, 75) normal (0, 0, 1) x axis (1, 0, 0)
  line L1 (-53.4167, -27.066) -> (-36.9655, 27.066)
  line L2 (-124, 27.066) -> (-53.4167, -27.066)
  line L3 (-36.9655, 27.066) -> (-124, 27.066)
  line L4 (-55.5648, -20.3777) -> (-42.3618, 23.066)
  line L5 (-112.2115, 23.066) -> (-55.5648, -20.3777)
  line L6 (-42.3618, 23.066) -> (-112.2115, 23.066)
  point P1 (0, 0)
  point P2 (-36.9655, 27.066)
  point P3 (-53.4167, -27.066)
  point P4 (-124, 27.066)
  dimension "d393" distance P1 P2 = 36.9655 (= "Linear Dimension-2")
  dimension "d394" distance P1 P2 = 27.066 (= "Linear Dimension-3")
  dimension "d395" distance P1 P3 = 53.4167 (= "Linear Dimension-4")
  dimension "d396" distance P1 P3 = 27.066 (= "Linear Dimension-5")
  dimension "d397" distance P1 P4 = 124 (= "Linear Dimension-6")
  dimension "d398" distance P1 P4 = 27.066 (= "Linear Dimension-7")
  dimension "d399" = 4 (= "memberWidth / 2")
extrude "Extrude6" cut sketch "B Facet 90 Triangle 2" profile of L5 L6 L4 against normal blind 4.7 (magnitude of "-( wall + 0.2 mm )")
sketch "B Facet 90 Triangle 3" plane through (0, 0, 75) normal (0, 0, 1) x axis (1, 0, 0)
  line L1 (-124, 27.066) -> (-53.4167, -27.066)
  line L2 (-124, -27.066) -> (-124, 27.066)
  line L3 (-53.4167, -27.066) -> (-124, -27.066)
  line L4 (-120, 18.9574) -> (-65.2053, -23.066)
  line L5 (-120, -23.066) -> (-120, 18.9574)
  line L6 (-65.2053, -23.066) -> (-120, -23.066)
  point P1 (0, 0)
  point P2 (-53.4167, -27.066)
  point P3 (-124, 27.066)
  point P4 (-124, -27.066)
  dimension "d402" distance P1 P2 = 53.4167 (= "Linear Dimension-2")
  dimension "d403" distance P1 P2 = 27.066 (= "Linear Dimension-3")
  dimension "d404" distance P1 P3 = 124 (= "Linear Dimension-4")
  dimension "d405" distance P1 P3 = 27.066 (= "Linear Dimension-5")
  dimension "d406" distance P1 P4 = 124 (= "Linear Dimension-6")
  dimension "d407" distance P1 P4 = 27.066 (= "Linear Dimension-7")
  dimension "d408" = -4 (= "-memberWidth / 2")
extrude "Extrude7" cut sketch "B Facet 90 Triangle 3" profile of L5 L6 L4 against normal blind 4.7 (magnitude of "-( wall + 0.2 mm )")
fillet "Fillet3" radius 1.5 (= "apertureRadius")
work_plane "WorkPlane7" RotateAngle 45 ExtraOffset 0
work_plane "WorkPlane8" AlongDistance 75 (= "bodyWidth / 2") ExtraOffset 0
sketch "B Facet 135 Triangle 1" plane through (0, -53.033, 53.033) normal (0, -0.7071, 0.7071) x axis (1, 0, 0)
  line L1 (62.2721, -27.066) -> (23.9949, 27.066)
  line L2 (-25.3367, 27.066) -> (62.2721, -27.066)
  line L3 (23.9949, 27.066) -> (-25.3367, 27.066)
  line L4 (47.6674, -13.34) -> (21.9244, 23.066)
  line L5 (-11.2532, 23.066) -> (47.6674, -13.34)
  line L6 (21.9244, 23.066) -> (-11.2532, 23.066)
  point P1 (0, 0)
  point P2 (23.9949, 27.066)
  point P3 (62.2721, -27.066)
  point P4 (-25.3367, 27.066)
  dimension "d417" distance P1 P2 = 23.9949 (= "Linear Dimension-2")
  dimension "d418" distance P1 P2 = 27.066 (= "Linear Dimension-3")
  dimension "d419" distance P1 P3 = 62.2721 (= "Linear Dimension-4")
  dimension "d420" distance P1 P3 = 27.066 (= "Linear Dimension-5")
  dimension "d421" distance P1 P4 = 25.3367 (= "Linear Dimension-6")
  dimension "d422" distance P1 P4 = 27.066 (= "Linear Dimension-7")
  dimension "d423" = 4 (= "memberWidth / 2")
extrude "Extrude8" cut sketch "B Facet 135 Triangle 1" profile of L5 L6 L4 against normal blind 4.7 (magnitude of "-( wall + 0.2 mm )")
sketch "B Facet 135 Triangle 2" plane through (0, -53.033, 53.033) normal (0, -0.7071, 0.7071) x axis (1, 0, 0)
  line L1 (-25.3367, 27.066) -> (62.2721, -27.066)
  line L2 (-61.9093, -27.066) -> (-25.3367, 27.066)
  line L3 (62.2721, -27.066) -> (-61.9093, -27.066)
  line L4 (-24.1722, 21.6445) -> (48.1886, -23.066)
  line L5 (-54.3795, -23.066) -> (-24.1722, 21.6445)
  line L6 (48.1886, -23.066) -> (-54.3795, -23.066)
  point P1 (0, 0)
  point P2 (62.2721, -27.066)
  point P3 (-25.3367, 27.066)
  point P4 (-61.9093, -27.066)
  dimension "d426" distance P1 P2 = 62.2721 (= "Linear Dimension-2")
  dimension "d427" distance P1 P2 = 27.066 (= "Linear Dimension-3")
  dimension "d428" distance P1 P3 = 25.3367 (= "Linear Dimension-4")
  dimension "d429" distance P1 P3 = 27.066 (= "Linear Dimension-5")
  dimension "d430" distance P1 P4 = 61.9093 (= "Linear Dimension-6")
  dimension "d431" distance P1 P4 = 27.066 (= "Linear Dimension-7")
  dimension "d432" = -4 (= "-memberWidth / 2")
extrude "Extrude9" cut sketch "B Facet 135 Triangle 2" profile of L5 L6 L4 against normal blind 4.7 (magnitude of "-( wall + 0.2 mm )")
sketch "B Facet 135 Triangle 3" plane through (0, -53.033, 53.033) normal (0, -0.7071, 0.7071) x axis (1, 0, 0)
  line L1 (-61.9093, -27.066) -> (-25.3367, 27.066)
  line L2 (-124, 27.066) -> (-61.9093, -27.066)
  line L3 (-25.3367, 27.066) -> (-124, 27.066)
  line L4 (-62.6909, -21.0779) -> (-32.8665, 23.066)
  line L5 (-113.325, 23.066) -> (-62.6909, -21.0779)
  line L6 (-32.8665, 23.066) -> (-113.325, 23.066)
  point P1 (0, 0)
  point P2 (-25.3367, 27.066)
  point P3 (-61.9093, -27.066)
  point P4 (-124, 27.066)
  dimension "d435" distance P1 P2 = 25.3367 (= "Linear Dimension-2")
  dimension "d436" distance P1 P2 = 27.066 (= "Linear Dimension-3")
  dimension "d437" distance P1 P3 = 61.9093 (= "Linear Dimension-4")
  dimension "d438" distance P1 P3 = 27.066 (= "Linear Dimension-5")
  dimension "d439" distance P1 P4 = 124 (= "Linear Dimension-6")
  dimension "d440" distance P1 P4 = 27.066 (= "Linear Dimension-7")
  dimension "d441" = 4 (= "memberWidth / 2")
extrude "Extrude10" cut sketch "B Facet 135 Triangle 3" profile of L5 L6 L4 against normal blind 4.7 (magnitude of "-( wall + 0.2 mm )")
sketch "B Facet 135 Triangle 4" plane through (0, -53.033, 53.033) normal (0, -0.7071, 0.7071) x axis (1, 0, 0)
  line L1 (-124, 27.066) -> (-61.9093, -27.066)
  line L2 (-124, -27.066) -> (-124, 27.066)
  line L3 (-61.9093, -27.066) -> (-124, -27.066)
  line L4 (-120, 18.272) -> (-72.5843, -23.066)
  line L5 (-120, -23.066) -> (-120, 18.272)
  line L6 (-72.5843, -23.066) -> (-120, -23.066)
  point P1 (0, 0)
  point P2 (-61.9093, -27.066)
  point P3 (-124, 27.066)
  point P4 (-124, -27.066)
  dimension "d444" distance P1 P2 = 61.9093 (= "Linear Dimension-2")
  dimension "d445" distance P1 P2 = 27.066 (= "Linear Dimension-3")
  dimension "d446" distance P1 P3 = 124 (= "Linear Dimension-4")
  dimension "d447" distance P1 P3 = 27.066 (= "Linear Dimension-5")
  dimension "d448" distance P1 P4 = 124 (= "Linear Dimension-6")
  dimension "d449" distance P1 P4 = 27.066 (= "Linear Dimension-7")
  dimension "d450" = -4 (= "-memberWidth / 2")
extrude "Extrude11" cut sketch "B Facet 135 Triangle 4" profile of L5 L6 L4 against normal blind 4.7 (magnitude of "-( wall + 0.2 mm )")
fillet "Fillet4" radius 1.5 (= "apertureRadius")
work_plane "WorkPlane9" RotateAngle 90 ExtraOffset 0
work_plane "WorkPlane10" AlongDistance 75 (= "bodyWidth / 2") ExtraOffset 0
sketch "B Facet 180 Triangle 1" plane through (0, -75, 0) normal (0, -1, 0) x axis (-1, 0, 0)
  line L1 (-65.1005, 27.066) -> (-65.1005, -27.066)
  line L2 (-2.067, -27.066) -> (-65.1005, 27.066)
  line L3 (-65.1005, -27.066) -> (-2.067, -27.066)
  line L4 (-61.1005, 18.3583) -> (-61.1005, -23.066)
  line L5 (-12.8644, -23.066) -> (-61.1005, 18.3583)
  line L6 (-61.1005, -23.066) -> (-12.8644, -23.066)
  point P1 (0, 0)
  point P2 (-65.1005, -27.066)
  point P3 (-65.1005, 27.066)
  point P4 (-2.067, -27.066)
  dimension "d459" distance P1 P2 = 65.1005 (= "Linear Dimension-2")
  dimension "d460" distance P1 P2 = 27.066 (= "Linear Dimension-3")
  dimension "d461" distance P1 P3 = 65.1005 (= "Linear Dimension-4")
  dimension "d462" distance P1 P3 = 27.066 (= "Linear Dimension-5")
  dimension "d463" distance P1 P4 = 2.067 (= "Linear Dimension-6")
  dimension "d464" distance P1 P4 = 27.066 (= "Linear Dimension-7")
  dimension "d465" = 4 (= "memberWidth / 2")
extrude "Extrude12" cut sketch "B Facet 180 Triangle 1" profile of L5 L6 L4 against normal blind 4.7 (magnitude of "-( wall + 0.2 mm )")
sketch "B Facet 180 Triangle 2" plane through (0, -75, 0) normal (0, -1, 0) x axis (-1, 0, 0)
  line L1 (-2.067, -27.066) -> (-65.1005, 27.066)
  line L2 (60.9665, 27.066) -> (-2.067, -27.066)
  line L3 (-65.1005, 27.066) -> (60.9665, 27.066)
  line L4 (-2.067, -21.7934) -> (-54.3031, 23.066)
  line L5 (50.1691, 23.066) -> (-2.067, -21.7934)
  line L6 (-54.3031, 23.066) -> (50.1691, 23.066)
  point P1 (0, 0)
  point P2 (-65.1005, 27.066)
  point P3 (-2.067, -27.066)
  point P4 (60.9665, 27.066)
  dimension "d468" distance P1 P2 = 65.1005 (= "Linear Dimension-2")
  dimension "d469" distance P1 P2 = 27.066 (= "Linear Dimension-3")
  dimension "d470" distance P1 P3 = 2.067 (= "Linear Dimension-4")
  dimension "d471" distance P1 P3 = 27.066 (= "Linear Dimension-5")
  dimension "d472" distance P1 P4 = 60.9665 (= "Linear Dimension-6")
  dimension "d473" distance P1 P4 = 27.066 (= "Linear Dimension-7")
  dimension "d474" = -4 (= "-memberWidth / 2")
extrude "Extrude13" cut sketch "B Facet 180 Triangle 2" profile of L5 L6 L4 against normal blind 4.7 (magnitude of "-( wall + 0.2 mm )")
